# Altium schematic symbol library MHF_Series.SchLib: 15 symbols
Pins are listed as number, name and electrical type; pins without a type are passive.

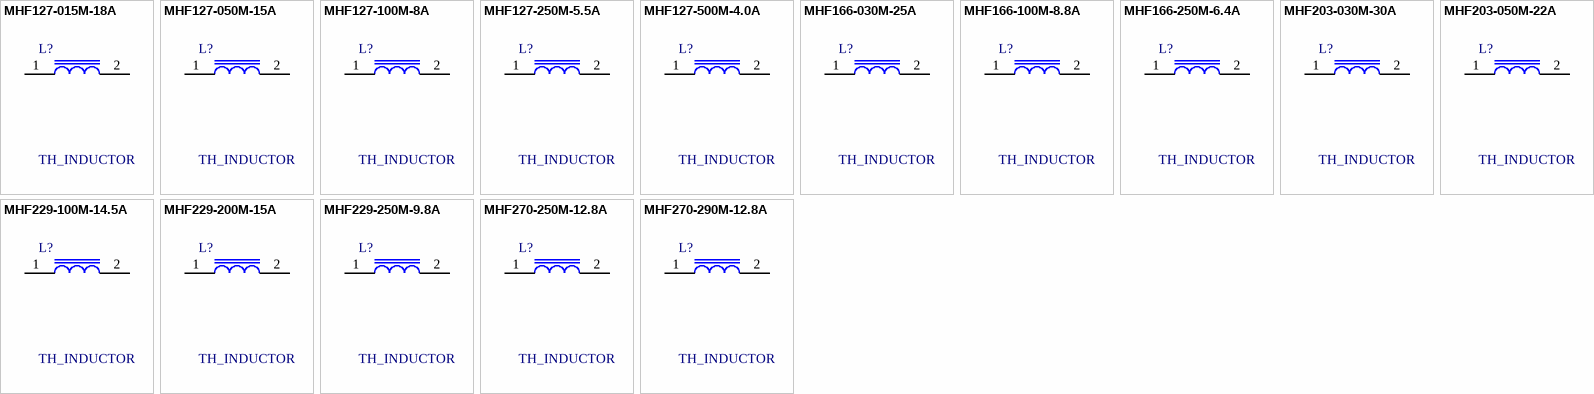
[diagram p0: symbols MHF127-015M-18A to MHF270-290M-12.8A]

## MHF127-015M-18A
designator L?, comment TH_INDUCTOR
POWER INDUCTOR A 18 A, uH 1.5 uH, mOhms 2 mOhms, 0.75 mm 19.05 mm, 0.4 mm 10.16 mm; Manufacturer #1: CWS; Current: 18 A; DCR: 2 mOhms; Inductance: 1.5 uH
footprint MHF127-015M-18A
pins: 1, 2

## MHF127-050M-15A
designator L?, comment TH_INDUCTOR
POWER INDUCTOR A 15 A, uH 5 uH, mOhms 3 mOhms, 0.75 mm 19.05 mm, 0.4 mm 10.16 mm; Manufacturer #1: CWS; Current: 15 A; DCR: 3 mOhms; Inductance: 5 uH
footprint MHF127-050M-15A
pins: 1, 2

## MHF127-100M-8A
designator L?, comment TH_INDUCTOR
POWER INDUCTOR A 8 A, uH 10 uH, mOhms 10 mOhms, 0.75 mm 19.05 mm, 0.4 mm 10.16 mm; Manufacturer #1: CWS; Current: 8 A; Inductance: 10 uH
footprint MHF127-100M-8A
pins: 1, 2

## MHF127-250M-5.5A
designator L?, comment TH_INDUCTOR
POWER INDUCTOR A 5.5 A, uH 25 uH, mOhms 20 mOhms, 0.75 mm 19.05 mm, 0.4 mm 10.16 mm; Manufacturer #1: CWS; Current: 5.5 A; Inductance: 25 uH
footprint MHF127-250M-5.5A
pins: 1, 2

## MHF127-500M-4.0A
designator L?, comment TH_INDUCTOR
POWER INDUCTOR A 4 A, uH 50 uH, mOhms 35 mOhms, 0.75 mm 19.05 mm, 0.4 mm 10.16 mm; Manufacturer #1: CWS; Current: 4 A; Inductance: 50 uH
footprint MHF127-500M-4.0A
pins: 1, 2

## MHF166-030M-25A
designator L?, comment TH_INDUCTOR
POWER INDUCTOR A 25 A, uH 3 uH, mOhms 2 mOhms, 1.16 mm 29.464 mm, 0.55 mm 13.97 mm; Manufacturer #1: CWS; Current: 25 A; DCR: 2 mOhms; Inductance: 3 uH
footprint MHF166-030M-25A
pins: 1, 2

## MHF166-100M-8.8A
designator L?, comment TH_INDUCTOR
POWER INDUCTOR A 8.8 A, uH 10 uH, mOhms 10 mOhms, 0.8 mm 20.32 mm, 0.5 mm 12.7 mm; Manufacturer #1: CWS; Current: 8.8 A; Inductance: 10 uH
footprint MHF166-100M-8.8A
pins: 1, 2

## MHF166-250M-6.4A
designator L?, comment TH_INDUCTOR
POWER INDUCTOR A 6.4 A, uH 25 uH, mOhms 17 mOhms, 0.8 mm 20.32 mm, 0.5 mm 12.7 mm; Manufacturer #1: CWS; Current: 6.4 A; Inductance: 25 uH
footprint MHF166-250M-6.4A
pins: 1, 2

## MHF203-030M-30A
designator L?, comment TH_INDUCTOR
POWER INDUCTOR A 30 A, uH 3 uH, mOhms 1 mOhms, 1.21 mm 30.734 mm, 0.685 mm 17.399 mm; Manufacturer #1: CWS; Current: 30 A; DCR: 1 mOhms; Inductance: 3 uH
footprint MHF203-030M-30A
pins: 1, 2

## MHF203-050M-22A
designator L?, comment TH_INDUCTOR
POWER INDUCTOR A 22 A, uH 5 uH, mOhms 2 mOhms, 1.21 mm 30.734 mm, 0.685 mm 17.399 mm; Manufacturer #1: CWS; Current: 22 A; DCR: 2 mOhms; Inductance: 5 uH
footprint MHF203-050M-22A
pins: 1, 2

## MHF229-100M-14.5A
designator L?, comment TH_INDUCTOR
POWER INDUCTOR A 14.5 A, uH 10 uH, mOhms 8 mOhms, 1.16 mm 29.464 mm, 0.55 mm 13.97 mm; Manufacturer #1: CWS; Current: 14.5 A; DCR: 8 mOhms; Inductance: 10 uH
footprint MHF229-100M-14.5A
pins: 1, 2

## MHF229-200M-15A
designator L?, comment TH_INDUCTOR
POWER INDUCTOR A 15 A, uH 20 uH, mOhms 8 mOhms, 1.21 mm 30.734 mm, 0.685 mm 17.399 mm; Manufacturer #1: CWS; Current: 15 A; DCR: 8 mOhms; Inductance: 20 uH
footprint MHF229-200M-15A
pins: 1, 2

## MHF229-250M-9.8A
designator L?, comment TH_INDUCTOR
POWER INDUCTOR A 9.8 A, uH 25 uH, mOhms 11 mOhms, 1.21 mm 30.734 mm, 0.685 mm 17.399 mm; Manufacturer #1: CWS; Current: 9.8 A; Inductance: 25 uH
footprint MHF229-250M-9.8A
pins: 1, 2

## MHF270-250M-12.8A
designator L?, comment TH_INDUCTOR
POWER INDUCTOR A 12.8 A, uH 25 uH, mOhms 7 mOhms, 1.45 mm 36.83 mm, 0.825 mm 20.955 mm; Manufacturer #1: CWS; Current: 12.8 A; DCR: 7 mOhms; Inductance: 25 uH
footprint MHF270-250M-12.8A
pins: 1, 2

## MHF270-290M-12.8A
designator L?, comment TH_INDUCTOR
POWER INDUCTOR A 12.8 A, uH 29 uH, mOhms 13 mOhms, 1.45 mm 36.83 mm, 0.825 mm 20.955 mm; Manufacturer #1: CWS; Current: 12.8 A; Inductance: 29 uH
footprint MHF270-290M-12.8A
pins: 1, 2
